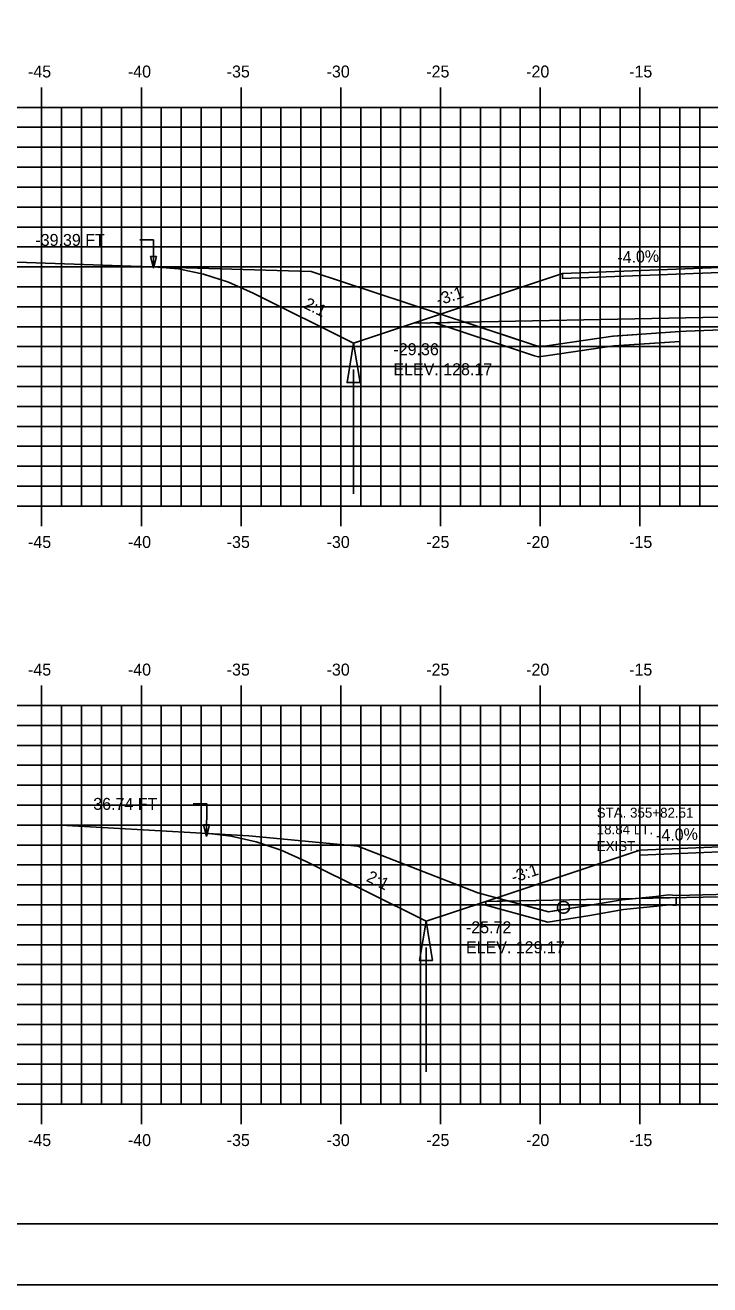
# Model space of a CAD drawing. Extents: x 1145638 to 1145808, y 608981 to 609091.
# Drawn here: x 1145674.8 to 1145709.1, y 608981.3 to 609044.5 of the extents above; entities that cross this region are included whole.
import ezdxf

# ---------------------------------------------------------------- set-up
doc = ezdxf.new("R2010")
doc.units = 0
for name, color, linetype in [('ANNOTATION', 7, 'Continuous'), ('BORDER', 7, 'Continuous'), ('D_Drainage_Ditch_Line', 7, 'Continuous'), ('D_Roadway_Edge_Shoulder', 7, 'Continuous'), ('D_Roadway_SlopeLines', 7, 'Continuous'), ('D_Roadway_SubGrade', 7, 'Continuous'), ('D_Text_Monospaced', 7, 'Continuous'), ('D_Text_Standard', 7, 'Continuous'), ('H_V ANNOTATION', 7, 'Continuous'), ('MAJOR', 7, 'Continuous'), ('MINOR', 7, 'Continuous'), ('PLOT BOUNDARY', 7, 'Continuous'), ('S_Drainage_Invert', 7, 'Continuous'), ('S_Roadway_Centerline', 7, 'Continuous'), ('SHADING', 7, 'Continuous')]:
    doc.layers.add(name, color=color, linetype=linetype)

msp = doc.modelspace()

# ---------------------------------------------------------------- linework, layer by layer
for points in [[(1145681.258, 609032.341), (1145682.508, 609032.231), (1145683.758, 609031.973), (1145685.008, 609031.568), (1145686.258, 609031.017), (1145691.284, 609028.504), (1145694.284, 609029.504), (1145701.76, 609031.996), (1145701.761, 609031.996), (1145709.645, 609032.311), (1145720.645, 609032.531), (1145731.645, 609032.311), (1145738.645, 609032.031), (1145746.177, 609029.52), (1145749.177, 609028.52), (1145749.6, 609028.71), (1145750.023, 609028.855), (1145750.446, 609028.957), (1145750.869, 609029.014)], [(1145683.903, 609003.924), (1145685.153, 609003.777), (1145686.403, 609003.494), (1145687.653, 609003.074), (1145688.903, 609002.517), (1145694.92, 608999.509), (1145697.92, 609000.509), (1145705.644, 609003.083), (1145705.645, 609003.083), (1145709.645, 609003.243), (1145720.645, 609003.463), (1145731.645, 609003.243), (1145738.645, 609002.963), (1145746.177, 609000.453), (1145749.177, 608999.453), (1145755.422, 609002.575), (1145756.672, 609003.138), (1145757.922, 609003.576), (1145759.172, 609003.888), (1145760.422, 609004.076)]]:
    msp.add_lwpolyline(points)
at = {"layer": 'BORDER'}
msp.add_lwpolyline([(1145645.645, 608984.335), (1145805.645, 608984.335), (1145805.645, 609089.335), (1145645.645, 609089.335)], close=True, dxfattribs=at)
at = {"layer": 'D_Drainage_Ditch_Line'}
for p, q in [((1145691.284, 609027.191), (1145691.284, 609020.948)), ((1145694.921, 608998.197), (1145694.92, 608991.953))]:
    msp.add_line(p, q, dxfattribs=at)
for points in [[(1145691.612, 609026.535), (1145690.956, 609026.535), (1145691.284, 609028.504)], [(1145695.249, 608997.54), (1145694.592, 608997.54), (1145694.92, 608999.509)]]:
    msp.add_lwpolyline(points, close=True, dxfattribs=at)
at = {"layer": 'D_Roadway_Edge_Shoulder'}
for points in [[(1145709.645, 609032.311), (1145701.761, 609031.996), (1145701.761, 609031.746), (1145709.645, 609032.061)], [(1145709.645, 609003.243), (1145705.645, 609003.083), (1145705.645, 609002.833), (1145709.645, 609002.993)]]:
    msp.add_lwpolyline(points, close=True, dxfattribs=at)
at = {"layer": 'D_Roadway_SlopeLines'}
for points in [[(1145691.284, 609028.504), (1145686.258, 609031.017), (1145685.008, 609031.568), (1145683.758, 609031.973), (1145682.508, 609032.231), (1145681.258, 609032.341)], [(1145694.284, 609029.504), (1145691.284, 609028.504)], [(1145694.92, 608999.509), (1145688.903, 609002.517), (1145687.653, 609003.074), (1145686.403, 609003.494), (1145685.153, 609003.777), (1145683.903, 609003.924)], [(1145697.92, 609000.509), (1145694.92, 608999.509)]]:
    msp.add_lwpolyline(points, dxfattribs=at)
at = {"layer": 'D_Roadway_SubGrade'}
for p, q in [((1145707.646, 609029.095), (1145707.646, 609028.595)), ((1145707.467, 609000.7), (1145707.467, 609000.31)), ((1145697.92, 609000.509), (1145697.92, 609000.315))]:
    msp.add_line(p, q, dxfattribs=at)
for points in [[(1145709.645, 609031.894), (1145709.645, 609032.061), (1145701.761, 609031.746), (1145701.761, 609031.996), (1145701.76, 609031.996), (1145694.284, 609029.504), (1145709.645, 609029.811)], [(1145709.645, 609002.827), (1145709.645, 609002.993), (1145705.645, 609002.833), (1145705.645, 609003.083), (1145705.644, 609003.083), (1145697.92, 609000.509), (1145709.645, 609000.743)]]:
    msp.add_lwpolyline(points, close=True, dxfattribs=at)
for points in [[(1145695.376, 609029.526), (1145700.35, 609027.881), (1145700.551, 609027.818), (1145701.042, 609027.888), (1145704.342, 609028.368), (1145704.364, 609028.37), (1145707.646, 609028.596)], [(1145697.92, 609000.315), (1145701.033, 608999.474), (1145703.128, 608999.807), (1145704.818, 609000.094), (1145706.495, 609000.262), (1145707.101, 609000.33), (1145707.459, 609000.31), (1145707.467, 609000.31)]]:
    msp.add_lwpolyline(points, dxfattribs=at)
at = {"layer": 'D_Text_Standard'}
for points in [[(1145681.258, 609032.267), (1145681.253, 609033.685), (1145680.573, 609033.685)], [(1145683.903, 609003.767), (1145683.93, 609005.399), (1145683.25, 609005.399)]]:
    msp.add_lwpolyline(points, dxfattribs=at)
for points in [[(1145681.258, 609032.267), (1145681.111, 609032.848), (1145681.402, 609032.849)], [(1145683.903, 609003.767), (1145683.767, 609004.352), (1145684.058, 609004.347)]]:
    msp.add_lwpolyline(points, close=True, dxfattribs=at)
at = {"layer": 'MAJOR'}
for p, q in [((1145675.645, 609041.337), (1145675.645, 609040.335)), ((1145680.645, 609041.337), (1145680.645, 609040.335)), ((1145685.645, 609041.337), (1145685.645, 609040.335)), ((1145690.645, 609041.337), (1145690.645, 609040.335)), ((1145695.645, 609041.337), (1145695.645, 609040.335)), ((1145700.645, 609041.337), (1145700.645, 609040.335)), ((1145705.645, 609041.337), (1145705.645, 609040.335)), ((1145650.645, 609040.335), (1145790.645, 609040.335)), ((1145650.645, 609040.335), (1145790.645, 609040.335)), ((1145675.645, 609020.335), (1145675.645, 609040.335)), ((1145680.645, 609020.335), (1145680.645, 609040.335)), ((1145685.645, 609020.335), (1145685.645, 609040.335)), ((1145690.645, 609020.335), (1145690.645, 609040.335)), ((1145695.645, 609020.335), (1145695.645, 609040.335)), ((1145700.645, 609020.335), (1145700.645, 609040.335)), ((1145705.645, 609020.335), (1145705.645, 609040.335)), ((1145650.645, 609035.335), (1145790.645, 609035.335)), ((1145650.645, 609030.335), (1145790.645, 609030.335)), ((1145650.645, 609025.335), (1145790.645, 609025.335)), ((1145650.645, 609020.335), (1145790.645, 609020.335)), ((1145650.645, 609020.335), (1145790.645, 609020.335)), ((1145675.645, 609019.333), (1145675.645, 609020.335)), ((1145680.645, 609019.333), (1145680.645, 609020.335)), ((1145685.645, 609019.333), (1145685.645, 609020.335)), ((1145690.645, 609019.333), (1145690.645, 609020.335)), ((1145695.645, 609019.333), (1145695.645, 609020.335)), ((1145700.645, 609019.333), (1145700.645, 609020.335)), ((1145705.645, 609019.333), (1145705.645, 609020.335)), ((1145675.645, 609011.337), (1145675.645, 609010.335)), ((1145680.645, 609011.337), (1145680.645, 609010.335)), ((1145685.645, 609011.337), (1145685.645, 609010.335)), ((1145690.645, 609011.337), (1145690.645, 609010.335)), ((1145695.645, 609011.337), (1145695.645, 609010.335)), ((1145700.645, 609011.337), (1145700.645, 609010.335)), ((1145705.645, 609011.337), (1145705.645, 609010.335)), ((1145650.645, 609010.335), (1145790.645, 609010.335)), ((1145650.645, 609010.335), (1145790.645, 609010.335)), ((1145675.645, 608990.335), (1145675.645, 609010.335)), ((1145680.645, 608990.335), (1145680.645, 609010.335)), ((1145685.645, 608990.335), (1145685.645, 609010.335)), ((1145690.645, 608990.335), (1145690.645, 609010.335)), ((1145695.645, 608990.335), (1145695.645, 609010.335)), ((1145700.645, 608990.335), (1145700.645, 609010.335)), ((1145705.645, 608990.335), (1145705.645, 609010.335)), ((1145650.645, 609005.335), (1145790.645, 609005.335)), ((1145650.645, 609000.335), (1145790.645, 609000.335)), ((1145650.645, 608995.335), (1145790.645, 608995.335)), ((1145650.645, 608990.335), (1145790.645, 608990.335)), ((1145650.645, 608990.335), (1145790.645, 608990.335)), ((1145675.645, 608989.333), (1145675.645, 608990.335)), ((1145680.645, 608989.333), (1145680.645, 608990.335)), ((1145685.645, 608989.333), (1145685.645, 608990.335)), ((1145690.645, 608989.333), (1145690.645, 608990.335)), ((1145695.645, 608989.333), (1145695.645, 608990.335)), ((1145700.645, 608989.333), (1145700.645, 608990.335)), ((1145705.645, 608989.333), (1145705.645, 608990.335))]:
    msp.add_line(p, q, dxfattribs=at)
at = {"layer": 'MINOR'}
for p, q in [((1145676.645, 609020.335), (1145676.645, 609040.335)), ((1145677.645, 609020.335), (1145677.645, 609040.335)), ((1145678.645, 609020.335), (1145678.645, 609040.335)), ((1145679.645, 609020.335), (1145679.645, 609040.335)), ((1145681.645, 609020.335), (1145681.645, 609040.335)), ((1145682.645, 609020.335), (1145682.645, 609040.335)), ((1145683.645, 609020.335), (1145683.645, 609040.335)), ((1145684.645, 609020.335), (1145684.645, 609040.335)), ((1145686.645, 609020.335), (1145686.645, 609040.335)), ((1145687.645, 609020.335), (1145687.645, 609040.335)), ((1145688.645, 609020.335), (1145688.645, 609040.335)), ((1145689.645, 609020.335), (1145689.645, 609040.335)), ((1145691.645, 609020.335), (1145691.645, 609040.335)), ((1145692.645, 609020.335), (1145692.645, 609040.335)), ((1145693.645, 609020.335), (1145693.645, 609040.335)), ((1145694.645, 609020.335), (1145694.645, 609040.335)), ((1145696.645, 609020.335), (1145696.645, 609040.335)), ((1145697.645, 609020.335), (1145697.645, 609040.335)), ((1145698.645, 609020.335), (1145698.645, 609040.335)), ((1145699.645, 609020.335), (1145699.645, 609040.335)), ((1145701.645, 609020.335), (1145701.645, 609040.335)), ((1145702.645, 609020.335), (1145702.645, 609040.335)), ((1145703.645, 609020.335), (1145703.645, 609040.335)), ((1145704.645, 609020.335), (1145704.645, 609040.335)), ((1145706.645, 609020.335), (1145706.645, 609040.335)), ((1145707.645, 609020.335), (1145707.645, 609040.335)), ((1145708.645, 609020.335), (1145708.645, 609040.335)), ((1145650.645, 609039.335), (1145790.645, 609039.335)), ((1145650.645, 609038.335), (1145790.645, 609038.335)), ((1145650.645, 609037.335), (1145790.645, 609037.335)), ((1145650.645, 609036.335), (1145790.645, 609036.335)), ((1145650.645, 609034.335), (1145790.645, 609034.335)), ((1145650.645, 609033.335), (1145790.645, 609033.335)), ((1145650.645, 609032.335), (1145790.645, 609032.335)), ((1145650.645, 609031.335), (1145790.645, 609031.335)), ((1145650.645, 609029.335), (1145790.645, 609029.335)), ((1145650.645, 609028.335), (1145790.645, 609028.335)), ((1145650.645, 609027.335), (1145790.645, 609027.335)), ((1145650.645, 609026.335), (1145790.645, 609026.335)), ((1145650.645, 609024.335), (1145790.645, 609024.335)), ((1145650.645, 609023.335), (1145790.645, 609023.335)), ((1145650.645, 609022.335), (1145790.645, 609022.335)), ((1145650.645, 609021.335), (1145790.645, 609021.335)), ((1145676.645, 608990.335), (1145676.645, 609010.335)), ((1145677.645, 608990.335), (1145677.645, 609010.335)), ((1145678.645, 608990.335), (1145678.645, 609010.335)), ((1145679.645, 608990.335), (1145679.645, 609010.335)), ((1145681.645, 608990.335), (1145681.645, 609010.335)), ((1145682.645, 608990.335), (1145682.645, 609010.335)), ((1145683.645, 608990.335), (1145683.645, 609010.335)), ((1145684.645, 608990.335), (1145684.645, 609010.335)), ((1145686.645, 608990.335), (1145686.645, 609010.335)), ((1145687.645, 608990.335), (1145687.645, 609010.335)), ((1145688.645, 608990.335), (1145688.645, 609010.335)), ((1145689.645, 608990.335), (1145689.645, 609010.335)), ((1145691.645, 608990.335), (1145691.645, 609010.335)), ((1145692.645, 608990.335), (1145692.645, 609010.335)), ((1145693.645, 608990.335), (1145693.645, 609010.335)), ((1145694.645, 608990.335), (1145694.645, 609010.335)), ((1145696.645, 608990.335), (1145696.645, 609010.335)), ((1145697.645, 608990.335), (1145697.645, 609010.335)), ((1145698.645, 608990.335), (1145698.645, 609010.335)), ((1145699.645, 608990.335), (1145699.645, 609010.335)), ((1145701.645, 608990.335), (1145701.645, 609010.335)), ((1145702.645, 608990.335), (1145702.645, 609010.335)), ((1145703.645, 608990.335), (1145703.645, 609010.335)), ((1145704.645, 608990.335), (1145704.645, 609010.335)), ((1145706.645, 608990.335), (1145706.645, 609010.335)), ((1145707.645, 608990.335), (1145707.645, 609010.335)), ((1145708.645, 608990.335), (1145708.645, 609010.335)), ((1145650.645, 609009.335), (1145790.645, 609009.335)), ((1145650.645, 609008.335), (1145790.645, 609008.335)), ((1145650.645, 609007.335), (1145790.645, 609007.335)), ((1145650.645, 609006.335), (1145790.645, 609006.335)), ((1145650.645, 609004.335), (1145790.645, 609004.335)), ((1145650.645, 609003.335), (1145790.645, 609003.335)), ((1145650.645, 609002.335), (1145790.645, 609002.335)), ((1145650.645, 609001.335), (1145790.645, 609001.335)), ((1145650.645, 608999.335), (1145790.645, 608999.335)), ((1145650.645, 608998.335), (1145790.645, 608998.335)), ((1145650.645, 608997.335), (1145790.645, 608997.335)), ((1145650.645, 608996.335), (1145790.645, 608996.335)), ((1145650.645, 608994.335), (1145790.645, 608994.335)), ((1145650.645, 608993.335), (1145790.645, 608993.335)), ((1145650.645, 608992.335), (1145790.645, 608992.335)), ((1145650.645, 608991.335), (1145790.645, 608991.335))]:
    msp.add_line(p, q, dxfattribs=at)
at = {"layer": 'PLOT BOUNDARY'}
msp.add_lwpolyline([(1145637.552, 608981.276), (1145807.552, 608981.276), (1145807.552, 609091.276), (1145637.552, 609091.276)], close=True, dxfattribs=at)
at = {"layer": 'S_Drainage_Invert'}
msp.add_circle((1145701.809, 609000.209), 0.3, dxfattribs=at)
at = {"layer": 'S_Roadway_Centerline'}
for points in [[(1145669.136, 609032.753), (1145680.62, 609032.361), (1145689.164, 609032.105), (1145700.503, 609028.355), (1145700.592, 609028.328), (1145700.97, 609028.382), (1145704.281, 609028.863), (1145704.322, 609028.867), (1145707.646, 609029.095), (1145707.961, 609029.103), (1145718.638, 609029.518), (1145719.177, 609029.498), (1145729.939, 609029.23), (1145730.211, 609029.201), (1145733.672, 609028.828), (1145734.305, 609028.732), (1145741.113, 609027.276), (1145743.374, 609027.926), (1145746.672, 609028.664), (1145751.599, 609029.075), (1145765.021, 609029.966)], [(1145665.284, 609004.253), (1145674.048, 609004.329), (1145676.611, 609004.338), (1145686.027, 609003.803), (1145691.493, 609003.283), (1145697.515, 609000.943), (1145701.06, 608999.985), (1145703.047, 609000.3), (1145704.751, 609000.59), (1145706.442, 609000.759), (1145707.087, 609000.832), (1145707.467, 609000.81), (1145715.52, 609001.007), (1145718.557, 609001.09), (1145727.194, 609000.779), (1145729.795, 609000.725), (1145730.727, 609000.642), (1145734.227, 609000.27), (1145736.145, 608999.62), (1145736.754, 608999.333), (1145745.298, 609002.239), (1145746.848, 609002.934), (1145749.998, 609003.03), (1145766.074, 609004.643)]]:
    msp.add_lwpolyline(points, dxfattribs=at)
at = {"layer": 'SHADING'}
for p, q in [((1145696.874, 609029.555), (1145695.376, 609029.526)), ((1145707.646, 609028.595), (1145707.646, 609029.095)), ((1145707.467, 609000.31), (1145707.467, 609000.7)), ((1145699.037, 609000.531), (1145697.92, 609000.509)), ((1145697.92, 609000.509), (1145697.92, 609000.315))]:
    msp.add_line(p, q, dxfattribs=at)
for points in [[(1145695.376, 609029.526), (1145700.35, 609027.881), (1145700.551, 609027.818), (1145701.042, 609027.888), (1145704.342, 609028.368), (1145707.646, 609028.595)], [(1145707.646, 609029.095), (1145704.281, 609028.863), (1145700.97, 609028.382), (1145700.503, 609028.355), (1145696.874, 609029.555)], [(1145705.447, 609000.659), (1145704.751, 609000.59), (1145703.047, 609000.3), (1145702.118, 609000.153), (1145702.103, 609000.15)], [(1145707.467, 609000.7), (1145706.443, 609000.679), (1145705.447, 609000.659)], [(1145697.92, 609000.315), (1145701.033, 608999.474), (1145703.128, 608999.807), (1145704.818, 609000.094), (1145706.495, 609000.262), (1145707.101, 609000.33), (1145707.467, 609000.31)], [(1145701.547, 609000.062), (1145701.06, 608999.985), (1145699.037, 609000.531)]]:
    msp.add_lwpolyline(points, dxfattribs=at)
msp.add_arc((1145701.809, 609000.209), 0.3, 209.39159, 348.65509, dxfattribs=at)

# ---------------------------------------------------------------- texts
at = {"layer": 'ANNOTATION'}
for s, rotation, p in [('-4.0%', 2.29061, (1145704.519, 609032.507)), ('-3:1', 18.43483, (1145695.539, 609030.376)), ('2:1', 333.43495, (1145688.738, 609030.295)), ('-4.0%', 2.29061, (1145706.461, 609003.517)), ('2:1', 333.43495, (1145691.879, 609001.548)), ('-3:1', 18.43482, (1145699.299, 609001.423))]:
    msp.add_text(s, height=0.6, rotation=rotation, dxfattribs=at).set_placement(p)
at = {"layer": 'D_Text_Monospaced'}
for s, height, p in [('STA. 355+82.51', 0.49998, (1145703.476, 609004.707)), ('18.84 LT.', 0.5, (1145703.476, 609003.873)), ('EXIST. ', 0.5, (1145703.476, 609003.033))]:
    msp.add_text(s, height=height, dxfattribs=at).set_placement(p)
at = {"layer": 'D_Text_Standard'}
for s, p in [('-39.39 FT', (1145675.333, 609033.385)), ('-29.36', (1145693.284, 609027.904)), ('ELEV. 128.17', (1145693.284, 609026.902)), ('-36.74 FT', (1145677.967, 609005.099)), ('-25.72', (1145696.921, 608998.909)), ('ELEV. 129.17', (1145696.921, 608997.907))]:
    msp.add_text(s, height=0.6, dxfattribs=at).set_placement(p)
at = {"layer": 'H_V ANNOTATION'}
for s, p in [('-45', (1145674.963, 609041.835)), ('-40', (1145679.971, 609041.835)), ('-35', (1145684.925, 609041.835)), ('-30', (1145689.933, 609041.835)), ('-25', (1145694.931, 609041.835)), ('-20', (1145699.939, 609041.835)), ('-15', (1145705.102, 609041.835)), ('-45', (1145674.963, 609018.235)), ('-40', (1145679.971, 609018.235)), ('-35', (1145684.925, 609018.235)), ('-30', (1145689.933, 609018.235)), ('-25', (1145694.931, 609018.235)), ('-20', (1145699.939, 609018.235)), ('-15', (1145705.102, 609018.235)), ('-45', (1145674.963, 609011.835)), ('-40', (1145679.971, 609011.835)), ('-35', (1145684.925, 609011.835)), ('-30', (1145689.933, 609011.835)), ('-25', (1145694.931, 609011.835)), ('-20', (1145699.939, 609011.835)), ('-15', (1145705.102, 609011.835)), ('-45', (1145674.963, 608988.235)), ('-40', (1145679.971, 608988.235)), ('-35', (1145684.925, 608988.235)), ('-30', (1145689.933, 608988.235)), ('-25', (1145694.931, 608988.235)), ('-20', (1145699.939, 608988.235)), ('-15', (1145705.102, 608988.235))]:
    msp.add_text(s, height=0.6, dxfattribs=at).set_placement(p)

doc.saveas('drawing.dxf')
